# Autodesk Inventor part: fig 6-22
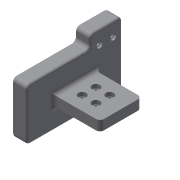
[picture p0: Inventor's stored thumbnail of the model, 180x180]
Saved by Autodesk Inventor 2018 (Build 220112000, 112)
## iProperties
Created: 2004-05
Part Number: fig 6-22
Document SubType Name: Modeling
Designer: CADCIM Technologies
Manufacturer: Standard
Standards Organization: Custom
Density: 1 g/cm^3
Material: Generic
Appearance: Default
Author: CADCIM Technologies
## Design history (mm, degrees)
node "Sketch1"
sketch "Sketch2"
  geometry: L1 (0, 0)-(0, 26.557); L2 (0, 26.557)-(31.986, 26.557); L3 (31.986, 26.557)-(31.986, 32.916); L4 (31.986, 32.916)-(48.42, 32.916); L5 (48.42, 32.916)-(48.42, 0); L6 (48.42, 0)-(0, 0)
  constraints: 12 end point, 4 parallel, 1 perpendicular, 1 vertical
extrude "Extrusion1" new body sketch "Sketch2" distance "d0" = 7.5; taper "d1" = 0 deg
workplane "Work Plane1"
sketch "Sketch3"
  geometry: L1 (7.5, 35.088)-(30.78, 35.088); L2 (30.78, 35.088)-(30.78, 13.871); L3 (30.78, 13.871)-(7.5, 13.871); L4 (7.5, 31.986)-(7.5, 48.42) reference; L5 (7.5, 0)-(7.5, 31.986) reference
  constraints: 6 end point, 2 point on line, 1 horizontal, 1 parallel, 1 perpendicular
extrude "Extrusion2" join sketch "Sketch3" distance "d3" = 5; taper "d4" = 0 deg
fillet "Fillet2" dims "d7" = 2
fillet "Fillet3" dims "d8" = 2
hole "Hole1" diameter "d11" = 3; stored, may be unused: countersink angle "d15" = 90 deg, drill point angle "d17" = 118 deg; dims "d9" = 7, "d10" = 16, "d12" = 6, "d13" = 4, "d14" = 2, "d16" = 8
pattern_linear "Rectangular Pattern1" dims "d20" = 7, "d23" = 7
hole "Hole2" diameter "d26" = 2; stored, may be unused: countersink angle "d30" = 90 deg, drill point angle "d32" = 118 deg; dims "d24" = 5, "d25" = 7, "d27" = 6, "d28" = 3, "d29" = 1, "d31" = 8
pattern_linear "Rectangular Pattern2" dims "d35" = 7
fillet "Fillet4" dims "d36" = 2
fillet "Fillet5" dims "d37" = 1
fillet "Fillet6" dims "d38" = 1
body "Solid1"
other parameters: "d2" = -11
